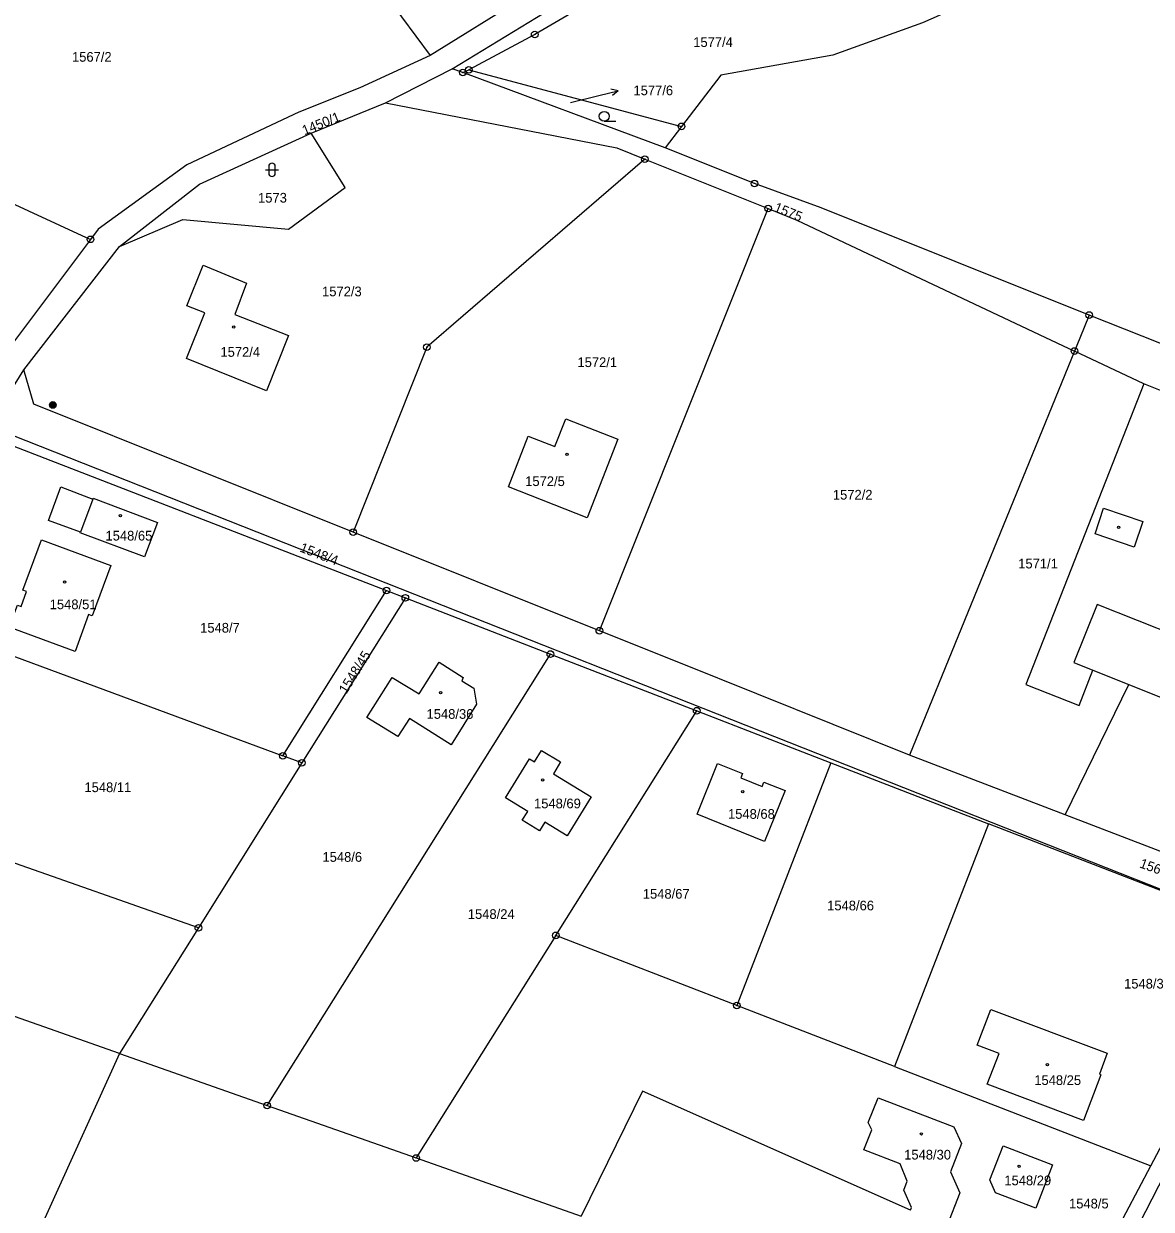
# Model space of a CAD drawing. Extents: x -587171 to -555306, y -1167727 to -1074732.
# Drawn here: x -559581.7 to -559411.8, y -1075730.3 to -1075551.6 of the extents above; entities that cross this region are included whole.
import ezdxf

# ---------------------------------------------------------------- set-up
doc = ezdxf.new("R2010")
doc.units = 0
for name, color, linetype in [('Hranice parcel', 7, 'Continuous'), ('Parcelní čísla', 7, 'Continuous'), ('Pop  PČ popisy', 7, 'Continuous'), ('Poz předměty', 7, 'Continuous'), ('Vnitřní kresba', 7, 'Continuous'), ('Značky bodu BP', 7, 'Continuous'), ('Značky budov', 7, 'Continuous'), ('Značky kultur', 7, 'Continuous')]:
    doc.layers.add(name, color=color, linetype=linetype)

msp = doc.modelspace()

# ---------------------------------------------------------------- linework, layer by layer
at = {"layer": 'Hranice parcel'}
for p, q in [((-559491.42, -1075538.43), (-559520.47, -1075556.43)), ((-559532.47, -1075540.24), (-559520.47, -1075556.43)), ((-559527.2, -1075563.57), (-559517.15, -1075558.42)), ((-559515.55, -1075559.01), (-559517.15, -1075558.42)), ((-559515.55, -1075559.01), (-559514.64, -1075558.6)), ((-559485.06, -1075570.35), (-559515.55, -1075559.01)), ((-559514.64, -1075558.6), (-559482.57, -1075567.11)), ((-559538.43, -1075568.15), (-559527.2, -1075563.57)), ((-559482.57, -1075567.11), (-559485.06, -1075570.35)), ((-559602.49, -1075569.96), (-559571.67, -1075584.14)), ((-559488.1, -1075572.05), (-559469.53, -1075579.5)), ((-559494.96, -1075643.12), (-559469.53, -1075579.5)), ((-559571.67, -1075584.14), (-559588.34, -1075606.32)), ((-559581.73, -1075603.81), (-559567.29, -1075585.24)), ((-559423.33, -1075600.97), (-559448.23, -1075661.87)), ((-559412.87, -1075605.9), (-559423.33, -1075600.97)), ((-559587.05, -1075612.28), (-559581.73, -1075603.81)), ((-559393.37, -1075688.85), (-559587.05, -1075612.28)), ((-559587.83, -1075613.53), (-559527.05, -1075637.07)), ((-559494.96, -1075643.12), (-559532.09, -1075628.26)), ((-559542.69, -1075661.97), (-559527.05, -1075637.07)), ((-559527.05, -1075637.07), (-559524.21, -1075638.17)), ((-559604.01, -1075639.32), (-559542.69, -1075661.97)), ((-559524.21, -1075638.17), (-559539.81, -1075663.03)), ((-559524.21, -1075638.17), (-559502.35, -1075646.64)), ((-559545.04, -1075714.69), (-559502.35, -1075646.64)), ((-559502.35, -1075646.64), (-559480.29, -1075655.18)), ((-559424.74, -1075670.89), (-559415.15, -1075651.22)), ((-559415.15, -1075651.22), (-559403.05, -1075656.08)), ((-559501.53, -1075689.04), (-559480.29, -1075655.18)), ((-559480.29, -1075655.18), (-559460.05, -1075663.02)), ((-559539.81, -1075663.03), (-559542.69, -1075661.97)), ((-559424.74, -1075670.89), (-559448.23, -1075661.87)), ((-559539.81, -1075663.03), (-559555.41, -1075687.89)), ((-559460.05, -1075663.02), (-559474.24, -1075699.61)), ((-559460.05, -1075663.02), (-559436.29, -1075672.22)), ((-559555.41, -1075687.89), (-559620.19, -1075665.1)), ((-559436.29, -1075672.22), (-559450.46, -1075708.82)), ((-559393.37, -1075688.85), (-559436.29, -1075672.22)), ((-559567.31, -1075706.86), (-559632.1, -1075684.07)), ((-559555.41, -1075687.89), (-559567.31, -1075706.86)), ((-559501.53, -1075689.04), (-559522.59, -1075722.59)), ((-559474.24, -1075699.61), (-559501.53, -1075689.04)), ((-559411.85, -1075723.77), (-559393.37, -1075688.85)), ((-559450.46, -1075708.82), (-559474.24, -1075699.61)), ((-559567.31, -1075706.86), (-559591.71, -1075760.7)), ((-559567.31, -1075706.86), (-559545.04, -1075714.69)), ((-559450.46, -1075708.82), (-559411.85, -1075723.77)), ((-559545.04, -1075714.69), (-559522.59, -1075722.59)), ((-559522.59, -1075722.59), (-559497.7, -1075731.34)), ((-559421.59, -1075742.17), (-559411.85, -1075723.77))]:
    msp.add_line(p, q, dxfattribs=at)
for points in [[(-559517.15, -1075558.42), (-559499.8, -1075547.82), (-559449.34, -1075522.27)], [(-559448.88, -1075523.04), (-559455.2, -1075526.61), (-559473.22, -1075535.49), (-559483.07, -1075540.59), (-559504.71, -1075553.28), (-559514.64, -1075558.6)], [(-559434.84, -1075546.43), (-559446.23, -1075551.49), (-559459.78, -1075556.36), (-559476.66, -1075559.39), (-559482.57, -1075567.11)], [(-559520.47, -1075556.43), (-559531.05, -1075561.31), (-559540.29, -1075564.95), (-559557.16, -1075572.9), (-559570.52, -1075582.61), (-559571.67, -1075584.14)], [(-559527.2, -1075563.57), (-559492.32, -1075570.36), (-559488.1, -1075572.05)], [(-559567.29, -1075585.24), (-559555.22, -1075575.82), (-559538.43, -1075568.15)], [(-559567.29, -1075585.24), (-559557.73, -1075581.13), (-559541.82, -1075582.6), (-559533.3, -1075576.34), (-559538.43, -1075568.15)], [(-559421.11, -1075595.55), (-559461.53, -1075579.41), (-559471.57, -1075575.71), (-559485.06, -1075570.35)], [(-559488.1, -1075572.05), (-559520.96, -1075600.4), (-559532.09, -1075628.26)], [(-559469.53, -1075579.5), (-559465.17, -1075581.25), (-559423.33, -1075600.97)], [(-559554.69, -1075588.04), (-559548.14, -1075590.73), (-559549.9, -1075595.45), (-559541.8, -1075598.64), (-559545.13, -1075606.95), (-559557.21, -1075602.09), (-559554.43, -1075595.23), (-559557.17, -1075594.16), (-559554.69, -1075588.04)], [(-559421.11, -1075595.55), (-559422.53, -1075599.02), (-559423.33, -1075600.97)], [(-559394.68, -1075605.81), (-559395.55, -1075605.46), (-559410.45, -1075599.8), (-559421.11, -1075595.55)], [(-559532.09, -1075628.26), (-559580.21, -1075609), (-559581.73, -1075603.81)], [(-559412.87, -1075605.9), (-559430.67, -1075651.22), (-559422.62, -1075654.41), (-559420.56, -1075649.05), (-559415.15, -1075651.22)], [(-559381.6, -1075618.55), (-559404.58, -1075609.22), (-559412.87, -1075605.9)], [(-559505.7, -1075613.78), (-559501.67, -1075615.36), (-559500.03, -1075611.17), (-559492.17, -1075614.24), (-559496.82, -1075626.1), (-559508.68, -1075621.46), (-559505.7, -1075613.78)], [(-559573.18, -1075628.27), (-559578.02, -1075626.49), (-559576.13, -1075621.43), (-559571.3, -1075623.28), (-559571.26, -1075623.17), (-559561.57, -1075626.81), (-559563.52, -1075632.01), (-559573.21, -1075628.38), (-559573.18, -1075628.27)], [(-559583.92, -1075642.57), (-559582.7, -1075639.28), (-559582.14, -1075639.48), (-559581.3, -1075637.23), (-559581.87, -1075637.02), (-559579.07, -1075629.42), (-559568.59, -1075633.31), (-559571.4, -1075640.89), (-559571.95, -1075640.69), (-559573.98, -1075646.25), (-559583.92, -1075642.57)], [(-559448.23, -1075661.87), (-559482.74, -1075648.01), (-559494.96, -1075643.12)], [(-559529.99, -1075656.18), (-559526.2, -1075650.15), (-559522.15, -1075652.66), (-559519.13, -1075647.87), (-559515.47, -1075650.17), (-559515.71, -1075650.67), (-559513.88, -1075651.79), (-559513.47, -1075654.21), (-559517.29, -1075660.31), (-559523.6, -1075656.37), (-559525.32, -1075659.07), (-559529.99, -1075656.18)], [(-559506.59, -1075671.7), (-559505.76, -1075670.37), (-559509.1, -1075668.29), (-559505.51, -1075662.42), (-559504.73, -1075662.9), (-559503.67, -1075661.17), (-559500.82, -1075662.9), (-559501.9, -1075664.67), (-559496.19, -1075668.15), (-559499.82, -1075674.04), (-559503.19, -1075671.97), (-559503.99, -1075673.26), (-559506.59, -1075671.7)], [(-559473.38, -1075664.62), (-559473.64, -1075665.29), (-559470.44, -1075666.62), (-559470.16, -1075665.93), (-559466.96, -1075667.2), (-559470.05, -1075674.89), (-559480.24, -1075670.79), (-559477.15, -1075663.12), (-559473.38, -1075664.62)], [(-559391.34, -1075685.13), (-559403.15, -1075679.18), (-559424.74, -1075670.89)], [(-559437.99, -1075705.59), (-559435.94, -1075700.23), (-559418.39, -1075706.8), (-559419.59, -1075709.97), (-559419.39, -1075710.04), (-559421.98, -1075716.94), (-559436.48, -1075711.47), (-559434.71, -1075706.82), (-559437.99, -1075705.59)], [(-559448.05, -1075730.43), (-559488.45, -1075712.5), (-559497.7, -1075731.34)], [(-559448.05, -1075730.43), (-559447.9, -1075730.05), (-559449.06, -1075727.42), (-559448.55, -1075726.08), (-559449.62, -1075723.49), (-559455.07, -1075721.38), (-559453.89, -1075718.33), (-559454.44, -1075717.24), (-559452.94, -1075713.51), (-559441.55, -1075717.87), (-559440.36, -1075720.4), (-559442.05, -1075724.67), (-559440.6, -1075727.83), (-559442.58, -1075732.86)], [(-559429.18, -1075730.16), (-559435.23, -1075727.83), (-559436.12, -1075725.89), (-559434.1, -1075720.78), (-559426.64, -1075723.63), (-559429.18, -1075730.16)]]:
    msp.add_lwpolyline(points, dxfattribs=at)
at = {"layer": 'Pop  PČ popisy'}
for p, q in [((-559499.3, -1075563.54), (-559495.06, -1075562.48)), ((-559495.06, -1075562.48), (-559492.15, -1075561.75)), ((-559492.15, -1075561.75), (-559493.24, -1075561.51)), ((-559492.15, -1075561.75), (-559493, -1075562.48))]:
    msp.add_line(p, q, dxfattribs=at)
at = {"layer": 'Poz předměty'}
for radius in [0.5, 0.4, 0.3, 0.2, 0.1]:
    msp.add_circle((-559577.35, -1075609.1), radius, dxfattribs=at)
at = {"layer": 'Vnitřní kresba'}
for p, q in [((-559571.3, -1075623.28), (-559573.18, -1075628.27)), ((-559420.21, -1075628.53), (-559418.98, -1075624.64)), ((-559418.98, -1075624.64), (-559413.04, -1075626.67)), ((-559413.04, -1075626.67), (-559414.35, -1075630.52)), ((-559414.35, -1075630.52), (-559420.21, -1075628.53)), ((-559419.91, -1075639.17), (-559423.44, -1075647.9)), ((-559403.77, -1075645.6), (-559419.91, -1075639.17)), ((-559423.44, -1075647.9), (-559420.56, -1075649.05)), ((-559419.23, -1075743.47), (-559389.37, -1075685.41))]:
    msp.add_line(p, q, dxfattribs=at)
at = {"layer": 'Značky bodu BP'}
for centre, radius in [((-559504.71, -1075553.28), 0.5), ((-559504.71, -1075553.28), 0.0303), ((-559515.55, -1075559.01), 0.5), ((-559515.55, -1075559.01), 0.0303), ((-559514.64, -1075558.6), 0.5), ((-559514.64, -1075558.6), 0.0303), ((-559482.57, -1075567.11), 0.5), ((-559482.57, -1075567.11), 0.0303), ((-559488.1, -1075572.05), 0.5), ((-559488.1, -1075572.05), 0.0303), ((-559471.57, -1075575.71), 0.5), ((-559471.57, -1075575.71), 0.0303), ((-559469.53, -1075579.5), 0.5), ((-559469.53, -1075579.5), 0.0303), ((-559571.67, -1075584.14), 0.5), ((-559571.67, -1075584.14), 0.0303), ((-559421.11, -1075595.55), 0.5), ((-559421.11, -1075595.55), 0.0303), ((-559520.96, -1075600.4), 0.5), ((-559520.96, -1075600.4), 0.0303), ((-559423.33, -1075600.97), 0.5), ((-559423.33, -1075600.97), 0.0303), ((-559532.09, -1075628.26), 0.5), ((-559532.09, -1075628.26), 0.0303), ((-559527.05, -1075637.07), 0.5), ((-559527.05, -1075637.07), 0.0303), ((-559524.21, -1075638.17), 0.5), ((-559524.21, -1075638.17), 0.0303), ((-559494.96, -1075643.12), 0.5), ((-559494.96, -1075643.12), 0.0303), ((-559502.35, -1075646.64), 0.5), ((-559502.35, -1075646.64), 0.0303), ((-559480.29, -1075655.18), 0.5), ((-559480.29, -1075655.18), 0.0303), ((-559542.69, -1075661.97), 0.5), ((-559542.69, -1075661.97), 0.0303), ((-559539.81, -1075663.03), 0.5), ((-559539.81, -1075663.03), 0.0303), ((-559555.41, -1075687.89), 0.5), ((-559555.41, -1075687.89), 0.0303), ((-559501.53, -1075689.04), 0.5), ((-559501.53, -1075689.04), 0.0303), ((-559474.24, -1075699.61), 0.5), ((-559474.24, -1075699.61), 0.0303), ((-559545.04, -1075714.69), 0.5), ((-559545.04, -1075714.69), 0.0303), ((-559522.59, -1075722.59), 0.5), ((-559522.59, -1075722.59), 0.0303)]:
    msp.add_circle(centre, radius, dxfattribs=at)
at = {"layer": 'Značky budov'}
for centre in [(-559550.07, -1075597.37), (-559499.84, -1075616.52), (-559567.16, -1075625.77), (-559416.7, -1075627.55), (-559575.57, -1075635.79), (-559518.89, -1075652.44), (-559503.51, -1075665.62), (-559473.34, -1075667.36), (-559427.43, -1075708.52), (-559446.41, -1075718.95), (-559431.68, -1075723.87)]:
    msp.add_circle(centre, 0.175, dxfattribs=at)
at = {"layer": 'Značky kultur'}
for p, q in [((-559494.23, -1075566.35), (-559492.48, -1075566.35)), ((-559544.81, -1075573.16), (-559544.81, -1075574.16)), ((-559543.81, -1075574.16), (-559543.81, -1075573.16)), ((-559545.31, -1075573.66), (-559543.31, -1075573.66))]:
    msp.add_line(p, q, dxfattribs=at)
msp.add_circle((-559494.23, -1075565.6), 0.75, dxfattribs=at)
for centre, start, end in [((-559544.31, -1075573.16), 0, 180), ((-559544.31, -1075574.16), 180, 359.9879)]:
    msp.add_arc(centre, 0.5, start, end, dxfattribs=at)

# ---------------------------------------------------------------- texts
at = {"layer": 'Parcelní čísla'}
for s, p in [('1577/4', (-559480.81, -1075555.15)), ('1567/2', (-559574.46, -1075557.37)), ('1577/6', (-559489.82, -1075562.42)), ('1573', (-559546.41, -1075578.6)), ('1572/3', (-559536.76, -1075592.72)), ('1572/4', (-559552.08, -1075601.84)), ('1572/1', (-559498.26, -1075603.39)), ('1572/5', (-559506.14, -1075621.32)), ('1572/2', (-559459.76, -1075623.36)), ('1548/65', (-559569.41, -1075629.53)), ('1571/1', (-559431.82, -1075633.74)), ('1548/51', (-559577.82, -1075639.88)), ('1548/7', (-559555.14, -1075643.41)), ('1548/36', (-559521.01, -1075656.4)), ('1548/11', (-559572.58, -1075667.45)), ('1548/69', (-559504.81, -1075669.89)), ('1548/68', (-559475.57, -1075671.47)), ('1548/6', (-559536.7, -1075677.95)), ('1548/67', (-559488.41, -1075683.51)), ('1548/66', (-559460.62, -1075685.27)), ('1548/24', (-559514.79, -1075686.56)), ('1548/3', (-559415.86, -1075697.05)), ('1548/25', (-559429.4, -1075711.59)), ('1548/30', (-559449.01, -1075722.82)), ('1548/29', (-559433.91, -1075726.7)), ('1548/5', (-559424.16, -1075730.19))]:
    msp.add_text(s, height=1.46, dxfattribs=at).set_placement(p)
for s, rotation, p in [('1450/1', 22, (-559539.42, -1075568.47)), ('1575', 338, (-559468.75, -1075579.87)), ('1548/4', 339, (-559540.24, -1075631.16)), ('1548/45', 58, (-559533.1, -1075652.73)), ('1568', 340, (-559413.64, -1075678.77))]:
    msp.add_text(s, height=1.46, rotation=rotation, dxfattribs=at).set_placement(p)

doc.saveas('drawing.dxf')
